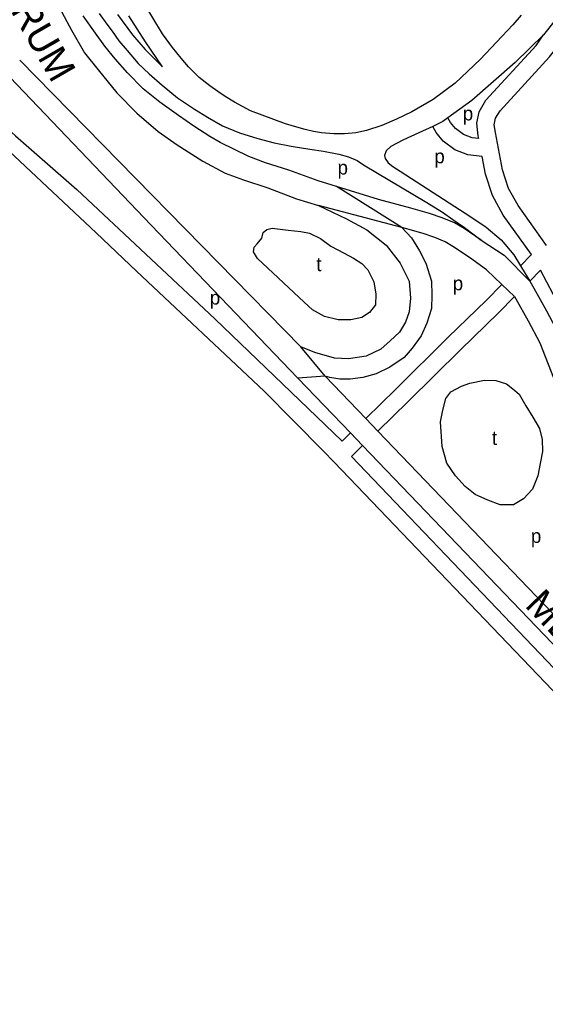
# Model space of a CAD drawing. Extents: x 154320 to 156262, y 382651 to 384180.
# Drawn here: x 155184.2 to 155334.5, y 382888.5 to 383173 of the extents above; entities that cross this region are included whole.
import ezdxf

# ---------------------------------------------------------------- set-up
doc = ezdxf.new("R2010")
doc.units = 0
for name, color, linetype in [('BLT_Basislijn', 7, 'Continuous'), ('BLT_Centroide', 7, 'Continuous'), ('BLT_Gemeentegrens', 7, 'Continuous'), ('BLT_Straatnaam_hoofdweg', 7, 'Continuous'), ('BLT_Vlakafsluiter', 7, 'Continuous')]:
    doc.layers.add(name, color=color, linetype=linetype)

msp = doc.modelspace()

# ---------------------------------------------------------------- linework, layer by layer
at = {"layer": 'BLT_Basislijn'}
for p, q in [((155221.78, 383114.39), (155263.73, 383070.65)), ((155327.41, 383102.74), (155330.6, 383105.96)), ((155327.41, 383102.74), (155330.08, 383098.33)), ((155330.08, 383098.33), (155333.17, 383101.45)), ((155322.11, 383097.38), (155325.72, 383093.92)), ((155263.73, 383070.65), (155278.78, 383054.95)), ((155271.54, 383071.17), (155283.16, 383059.05)), ((155278.78, 383054.95), (155276.41, 383052.62)), ((155278.78, 383054.95), (155282.24, 383051.34)), ((155286.62, 383055.44), (155368.92, 382969.61)), ((155282.24, 383051.34), (155279.11, 383048.25)), ((155282.24, 383051.34), (155361.88, 382968.28))]:
    msp.add_line(p, q, dxfattribs=at)
for points in [[(155320.24, 383140.84), (155319.93, 383143.05), (155320.31, 383144.91), (155321.59, 383147.08), (155335.71, 383162.43), (155344.62, 383173.54), (155351.02, 383183), (155360.81, 383198.54), (155367.06, 383211.27), (155374.73, 383230.39), (155382.06, 383254.72), (155389.26, 383281.18), (155396.19, 383313.18)], [(155179.8, 383233.1), (155181.73, 383219.99), (155184.12, 383208.96), (155186.05, 383200.91), (155187.54, 383194.95), (155190.37, 383187.8), (155192.61, 383182.58), (155195.58, 383176.47), (155199.01, 383170.07), (155202.73, 383163.66), (155206.61, 383158.74), (155211.97, 383152.18), (155217.63, 383146.37), (155223.74, 383141.16), (155229.25, 383137.28), (155236.55, 383132.66), (155242.95, 383129.23), (155248.17, 383127.3), (155255.17, 383125.06), (155263.36, 383121.93), (155269.62, 383120)], [(155360, 383208.17), (155354.11, 383197.62), (155347.61, 383187.46), (155341.47, 383178.13), (155334.03, 383168.79)], [(155327.61, 383174.35), (155325.21, 383171.61), (155315.85, 383161.76), (155308.75, 383154.98), (155302.45, 383150.3), (155296.32, 383146.75), (155291.96, 383144.65), (155287.76, 383142.87), (155283.41, 383141.42), (155280.34, 383140.77), (155277.11, 383140.45), (155274.05, 383140.45), (155270.5, 383140.77), (155268.24, 383141.1), (155265.82, 383141.74), (155262.75, 383142.55), (155260.17, 383143.36), (155250.16, 383147.07), (155245.64, 383149.49), (155242.9, 383151.11), (155240.8, 383152.56), (155238.54, 383154.17), (155235.47, 383156.59), (155232.41, 383159.66), (155230.31, 383162.08), (155227.89, 383165.15), (155224.98, 383169.03), (155219.5, 383178.23)], [(155206.86, 383174.91), (155209.09, 383171.85), (155210.58, 383169.77), (155212.52, 383167.08), (155214.9, 383164.25), (155218.1, 383160.6), (155221.23, 383157.62), (155224.95, 383154.34), (155229.27, 383150.77), (155234.19, 383147.56), (155237.91, 383145.25), (155242.16, 383142.79), (155247.08, 383140.71), (155252.29, 383139.14), (155256.98, 383137.88), (155261.82, 383136.91), (155267.18, 383136.09), (155271.06, 383135.49), (155275.45, 383134.67), (155278.21, 383133.85), (155280.74, 383132.88), (155282.53, 383131.62), (155300.63, 383120.81), (155305.1, 383118.06), (155308.08, 383115.97), (155311.43, 383113.66), (155316.19, 383110.09)], [(155212.16, 383174.59), (155216.41, 383168.8), (155220.08, 383164.54), (155225.03, 383159.58), (155220.19, 383166.79), (155215.35, 383174.23)], [(155274.78, 383125.43), (155269.5, 383127.07), (155261.15, 383130.05), (155254.45, 383132.14), (155249.76, 383134), (155245.59, 383135.94), (155241.49, 383138.03), (155238.59, 383139.74), (155233.97, 383142.64), (155229.57, 383145.7), (155224.21, 383149.5), (155219.52, 383153.37), (155214.97, 383157.92), (155211.47, 383161.87), (155208.49, 383165.52), (155205.81, 383169.24), (155202.31, 383174.16)], [(155334.03, 383168.79), (155325.88, 383160.88), (155313.48, 383150.01), (155306.66, 383145.04)], [(155315.32, 383139.92), (155314.93, 383143.55), (155315.58, 383146.73), (155317.55, 383150.08), (155331.91, 383165.69), (155334.03, 383168.79)], [(155156.57, 383164.13), (155169.64, 383152.12), (155182.93, 383139.9), (155200.5, 383124.59)], [(155264.55, 383079.61), (155184.2, 383161.54)], [(155179.3, 383158.75), (155221.78, 383114.39)], [(155305.22, 383143.99), (155302.3, 383142.59)], [(155306.66, 383145.04), (155305.22, 383143.99)], [(155315.47, 383139.15), (155313.55, 383139.36), (155311.1, 383140.28), (155308.83, 383142), (155307.41, 383143.73), (155306.66, 383145.04)], [(155302.3, 383142.59), (155298.36, 383140.71), (155293.75, 383138.62), (155290.32, 383136.83), (155288.98, 383135.64), (155288.53, 383134.3), (155288.68, 383133.41), (155289.58, 383132.21), (155290.92, 383131.17), (155293, 383129.83), (155313.26, 383116.72), (155317.58, 383113.74), (155321.9, 383110.16), (155325.47, 383105.84), (155327.41, 383102.74)], [(155316.43, 383134.01), (155312.38, 383134.46), (155308.66, 383135.85), (155305.34, 383138.37), (155303.28, 383140.88), (155302.3, 383142.59)], [(155334.89, 383108.54), (155326.74, 383119.93), (155324.03, 383124.81), (155322.23, 383130.21), (155320.24, 383140.84)], [(155315.47, 383139.15), (155315.32, 383139.92)], [(155330.6, 383105.96), (155322.51, 383117.26), (155319.44, 383122.79), (155317.38, 383128.96), (155316.43, 383134.01)], [(155276.41, 383052.62), (155240.01, 383087.59), (155200.5, 383124.59)], [(155316.19, 383110.09), (155311.28, 383113.36), (155308.52, 383115), (155305.02, 383116.42), (155301.37, 383117.69), (155296.08, 383119.18), (155286.85, 383121.71), (155274.78, 383125.43)], [(155269.62, 383120), (155277.66, 383116.12), (155283.47, 383112.99), (155288.98, 383108.67), (155293, 383103.45), (155295.54, 383098.39), (155295.98, 383093.47), (155295.54, 383089.59), (155294.49, 383086.61), (155292.85, 383083.78), (155290.17, 383081.25), (155287.49, 383078.87), (155283.32, 383076.93), (155278.26, 383076.18), (155274.23, 383076.33), (155268.57, 383077.97), (155264.55, 383079.61)], [(155293.48, 383113.67), (155296.28, 383110.76), (155298.51, 383107.03), (155300.3, 383103.45), (155301.94, 383098.39), (155302.09, 383094.36), (155301.94, 383090.49), (155300.6, 383086.32), (155298.96, 383082.74), (155296.43, 383079.16), (155294.19, 383076.48), (155290.02, 383073.8), (155286.15, 383071.86), (155282.28, 383070.82), (155278.7, 383070.37), (155275.72, 383070.37), (155272.89, 383070.82), (155271.54, 383071.17)], [(155322.11, 383097.38), (155317.68, 383101.62), (155312.86, 383105.09), (155308.08, 383108.29), (155305.85, 383109.61), (155302.91, 383110.8), (155299.57, 383111.96), (155294.48, 383113.39), (155293.48, 383113.67)], [(155452.48, 382890.34), (155451.08, 382897.36), (155450.16, 382900.07), (155449.01, 382901.52), (155440.46, 382910.55), (155426.53, 382925.2), (155374.6, 382980.08), (155368.26, 382988), (155363.39, 382996.14), (155359.25, 383004.63), (155355.88, 383013.44), (155353.21, 383023.73), (155351.64, 383034.45), (155350.76, 383045.31), (155349.91, 383053.88), (155348.58, 383062.03), (155347.18, 383068.49), (155343.2, 383080.69), (155338.57, 383091.19), (155333.17, 383101.45)], [(155330.08, 383098.33), (155331.28, 383096.3), (155334.86, 383089.89), (155338.43, 383083.19), (155342.6, 383072.61), (155344.69, 383064.71), (155345.88, 383058), (155347.07, 383051.15), (155347.37, 383042.95), (155347.82, 383037.14), (155348.42, 383027.75), (155349.01, 383023.28), (155350.05, 383018.96), (155351.99, 383012.26), (155353.63, 383007.64), (155355.71, 383002.42)], [(155322.11, 383097.38), (155317.62, 383092.85), (155306.77, 383082.32), (155291.76, 383067.49), (155283.16, 383059.05)], [(155325.72, 383093.92), (155321.14, 383089.29), (155310.27, 383078.74), (155295.26, 383063.93), (155286.62, 383055.44)], [(155325.72, 383093.92), (155326.08, 383093.31), (155329.59, 383087.02), (155332.98, 383080.67), (155336.89, 383070.73), (155338.83, 383063.42), (155339.97, 383056.96), (155341.09, 383050.52), (155341.38, 383042.61), (155341.83, 383036.72), (155342.44, 383027.17), (155343.11, 383022.18), (155344.25, 383017.42), (155346.28, 383010.42), (155348.01, 383005.52), (155350.2, 383000.05)], [(155283.16, 383059.05), (155286.62, 383055.44)], [(155437.28, 382888.54), (155432.69, 382889.83), (155430.73, 382890.72), (155428.07, 382892.62), (155424.14, 382896.55), (155410.6, 382910.72), (155326.81, 382998.3), (155279.11, 383048.25)]]:
    msp.add_lwpolyline(points, dxfattribs=at)
for points in [[(155261, 383112.91), (155264.54, 383112.56), (155267.11, 383112.03), (155270.21, 383110.52), (155273.14, 383108.39), (155276.99, 383106.31), (155279.61, 383104.89), (155282.04, 383103.43), (155283.77, 383101.61), (155285.45, 383098.2), (155286.03, 383094.61), (155285.94, 383091.6), (155284.26, 383089.43), (155282, 383087.92), (155278.9, 383087.3), (155275.22, 383087.26), (155271.32, 383088.28), (155267.95, 383090.14), (155265.52, 383092.31), (155252.18, 383104.85), (155251.03, 383106.75), (155251.2, 383108.08), (155252.13, 383109.01), (155253.46, 383110.65), (155253.82, 383112.25), (155254.88, 383113.09), (155256.39, 383113.53)], [(155312.96, 383069.18), (155317.15, 383070.01), (155320.36, 383069.96), (155323.43, 383069.03), (155325.24, 383067.52), (155327.04, 383066.01), (155328.99, 383062.75), (155330.94, 383059.48), (155332.88, 383056.22), (155333.66, 383053.1), (155333.71, 383049.69), (155333.03, 383046.18), (155332.35, 383042.68), (155330.84, 383038.93), (155328.3, 383036.15), (155325.38, 383034.4), (155321.63, 383034.44), (155318.07, 383035.71), (155314.42, 383037.32), (155311.59, 383039.66), (155308.87, 383042.68), (155306.38, 383046.28), (155304.97, 383051.06), (155304.53, 383058.12), (155305.16, 383061.43), (155306.09, 383064.8), (155307.45, 383066.7), (155310.57, 383068.3)]]:
    msp.add_lwpolyline(points, close=True, dxfattribs=at)
at = {"layer": 'BLT_Gemeentegrens'}
msp.add_line((155274.11, 383046.56), (155349.67, 382967.76), dxfattribs=at)
msp.add_lwpolyline([(155157.57, 383157.52), (155206, 383112.13), (155217.58, 383101.23), (155254.12, 383066.87), (155270.93, 383049.87), (155274.11, 383046.56)], dxfattribs=at)
at = {"layer": 'BLT_Vlakafsluiter'}
for p, q in [((155293.48, 383113.67), (155274.78, 383125.43)), ((155293.48, 383113.67), (155269.62, 383120)), ((155271.54, 383071.17), (155264.55, 383079.61)), ((155271.54, 383071.17), (155263.73, 383070.65))]:
    msp.add_line(p, q, dxfattribs=at)
msp.add_lwpolyline([(155316.19, 383110.09), (155322.73, 383105.74), (155330.08, 383098.33)], dxfattribs=at)

# ---------------------------------------------------------------- texts
at = {"layer": 'BLT_Centroide'}
for s, p in [('p', (155310.91, 383144.3)), ('p', (155302.78, 383132.04)), ('p', (155275.1, 383128.82)), ('t', (155269.02, 383101.21)), ('p', (155308.04, 383095.73)), ('p', (155238.55, 383091.65)), ('t', (155319.24, 383051.54)), ('p', (155330.4, 383023.51))]:
    msp.add_text(s, height=4, dxfattribs=at).set_placement(p)
at = {"layer": 'BLT_Straatnaam_hoofdweg'}
for s, rotation, p in [('PARK FORUM', 300, (155157.95, 383216.39)), ('MEERHOVENDREEF', 313.7994, (155328.39, 383005.47))]:
    msp.add_text(s, height=8, rotation=rotation, dxfattribs=at).set_placement(p)

doc.saveas('drawing.dxf')
